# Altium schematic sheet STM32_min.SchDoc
size A; SheetNumber: 2; SheetTotal: 5
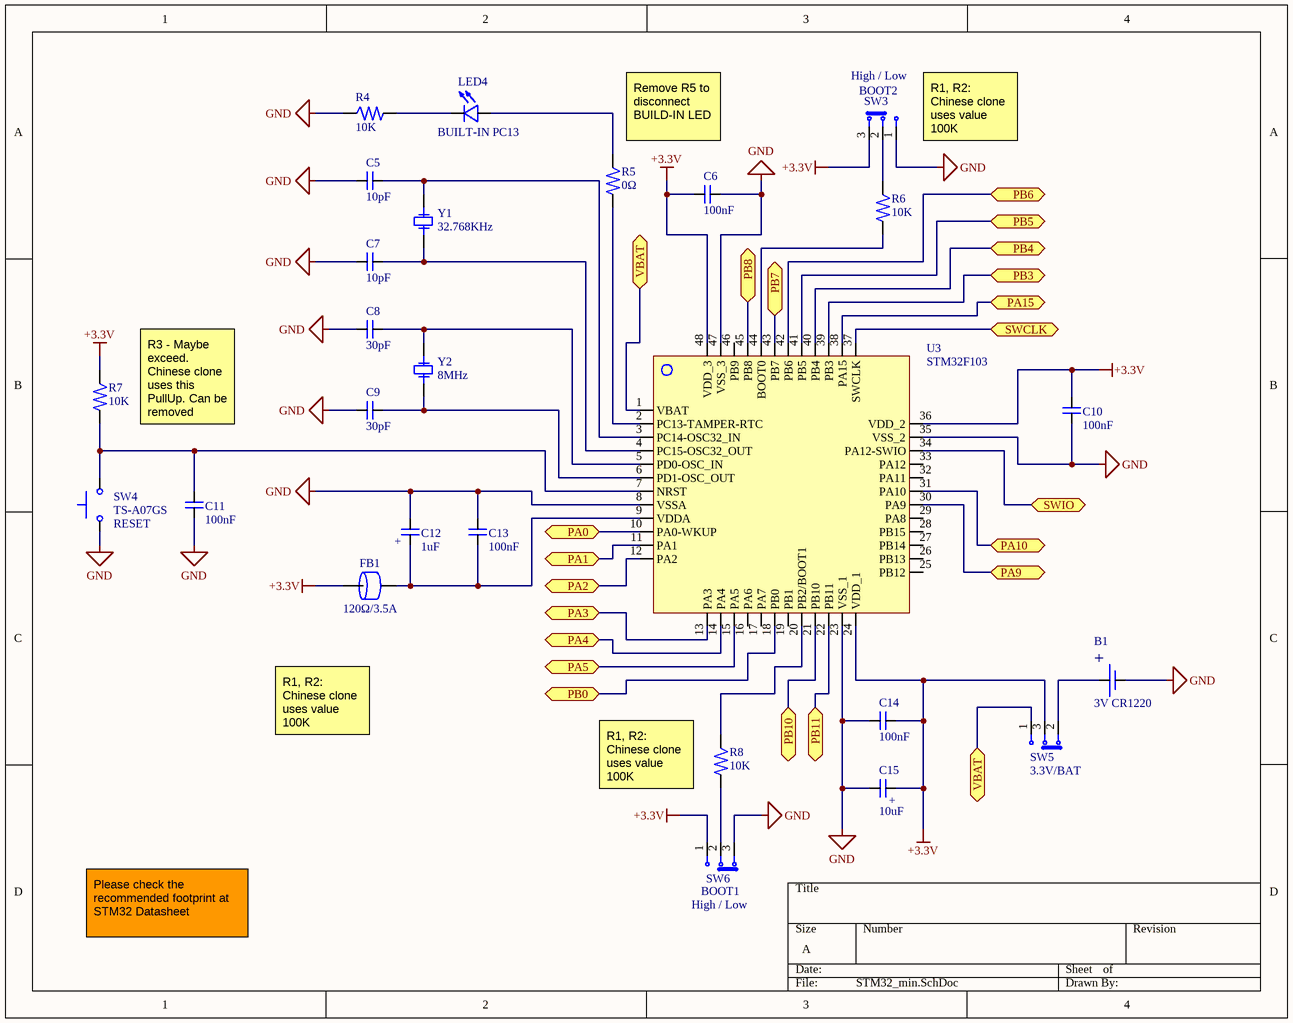
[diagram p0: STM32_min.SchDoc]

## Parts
B1  3V CR1220  [THT_BH-25T-GLD]
C5  10pF  [SMT_CAP_CER_MODEL_0805(2012)_SAMSUNG]
C6  100nF  [SMT_CAP_MODEL_1206(3216)_SAMSUNG]
C7  10pF  [SMT_CAP_CER_MODEL_0805(2012)_SAMSUNG]
C8  30pF  [SMT_CAP_MODEL_1206(3216)_SAMSUNG]
C9  30pF  [SMT_CAP_MODEL_1206(3216)_SAMSUNG]
C10  100nF  [SMT_CAP_MODEL_1206(3216)_SAMSUNG]
C11  100nF  [SMT_CAP_MODEL_1206(3216)_SAMSUNG]
C12  1uF  [SMT_CAP_TANT_MODEL_1206(3216)_KYOCERA]
C13  100nF  [SMT_CAP_MODEL_1206(3216)_SAMSUNG]
C14  100nF  [SMT_CAP_MODEL_1206(3216)_SAMSUNG]
C15  10uF  [SMT_CAP_TANT_MODEL_1210(3528)_KYOCERA]
FB1  120Ω/3.5A  [SMT_FERR_BEAD_MODEL_1206(3216)_MURATA]
LED4  BUILT-IN PC13  [DIOM2012X18N]
R4  10K  [SMT_RES_MODEL_1206(3216)_ROHM]
R5  0Ω  [SMT_RES_MODEL_1206(3216)_ROHM]
R6  10K  [SMT_RES_MODEL_1206(3216)_ROHM]
R7  10K  [SMT_RES_MODEL_1206(3216)_ROHM]
R8  10K  [SMT_RES_MODEL_1206(3216)_ROHM]
SW3  BOOT2  [SMT_SWW_SS-B90AP_DAWNING]
SW4  TS-A07GS  [SMT_TSW-A07GS]
SW5  3.3V/BAT  [THT_SSW_ESP1010]
SW6  BOOT1  [SMT_SWW_SS-B90AP_DAWNING]
U3  STM32F103  [SMT_IC_STM32F103]
Y1  32.768KHz  [SMT_XTAL_FC-135_EPSON]
Y2  8MHz  [SMT_XTAL_ATS08ASM-1E]

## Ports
PA0 (bidir), PA1 (bidir), PA2 (bidir), PA3 (bidir), PA4 (bidir), PA5 (bidir), PA9 (bidir), PA10 (bidir), PA15 (bidir), PB0 (bidir), PB3 (bidir), PB4 (bidir), PB5 (bidir), PB6 (bidir), PB7 (bidir), PB8 (bidir), PB10 (bidir), PB11 (bidir), SWCLK (bidir), SWIO (bidir), VBAT (bidir)

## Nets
+3.3V: C6.1 C10.1 C14.1 C15.1 FB1.1 R7.2 SW3.3 SW5.3 SW6.1 U3.24(VDD_1) U3.36(VDD_2) U3.48(VDD_3)
GND: B1.2(V-) C5.1 C6.2 C7.1 C8.1 C9.1 C10.2 C11.1 C12.2 C13.2 C14.2 C15.2 R4.2 SW3.1 SW4.1 SW6.3 U3.8(VSSA) U3.23(VSS_1) U3.35(VSS_2) U3.47(VSS_3)
PA0: U3.10(PA0-WKUP) ; port PA0
PA1: U3.11(PA1) ; port PA1
PA2: U3.12(PA2) ; port PA2
PA3: U3.13(PA3) ; port PA3
PA4: U3.14(PA4) ; port PA4
PA5: U3.15(PA5) ; port PA5
PA9: U3.30(PA9) ; port PA9
PA10: U3.31(PA10) ; port PA10
PA15: U3.38(PA15) ; port PA15
PB0: U3.18(PB0) ; port PB0
PB3: U3.39(PB3) ; port PB3
PB4: U3.40(PB4) ; port PB4
PB5: U3.41(PB5) ; port PB5
PB6: U3.42(PB6) ; port PB6
PB7: U3.43(PB7) ; port PB7
PB8: U3.45(PB8) ; port PB8
PB10: U3.21(PB10) ; port PB10
PB11: U3.22(PB11) ; port PB11
SWCLK: U3.37(SWCLK) ; port SWCLK
SWIO: U3.34(PA12-SWIO) ; port SWIO
VBAT: SW5.1 U3.1(VBAT) ; port VBAT
NetB1_1: B1.1(V+) SW5.2
NetC5_2: C5.2 U3.3(PC14-OSC32_IN) Y1.2
NetC7_2: C7.2 U3.4(PC15-OSC32_OUT) Y1.1
NetC8_2: C8.2 U3.5(PD0-OSC_IN) Y2.2
NetC9_2: C9.2 U3.6(PD1-OSC_OUT) Y2.1
NetC11_2: C11.2 R7.1 SW4.2 U3.7(NRST)
NetC12_1: C12.1 C13.1 FB1.2 U3.9(VDDA)
NetLED4_1: LED4.1 R5.2
NetLED4_2: LED4.2 R4.1
NetR5_1: R5.1 U3.2(PC13-TAMPER-RTC)
NetR6_1: R6.1 U3.44(BOOT0)
NetR6_2: R6.2 SW3.2
NetR8_1: R8.1 SW6.2
NetR8_2: R8.2 U3.20(PB2/BOOT1)

Not connected (* = marked no-connect by the designer): U3 16(PA6) 17(PA7) 19(PB1) 25(PB12) 26(PB13) 27(PB14) 28(PB15) 29(PA8) 32(PA11) 33(PA12) 46(PB9)

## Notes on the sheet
- (near SW3) High / Low
- (near R5) Remove R5 to disconnect BUILD-IN LED
- (near SW3) R1, R2: Chinese clone uses value 100K
- (near R7) R3 - Maybe exceed. Chinese clone uses this PullUp. Can be removed
- (near SW4) RESET
- R1, R2: Chinese clone uses value 100K
- (near R8) R1, R2: Chinese clone uses value 100K
- (near SW6) High / Low
- Please check the recommended footprint at STM32 Datasheet

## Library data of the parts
B1 = THT_BH-25T-GLD: Battery Holder for CR-2032 Type Battery BH-25T-GLD
C5 C7 = SMT_CAP_CER_MODEL_0805(2012)_SAMSUNG: SMT SAMSUNG Ceramic Capacitor MODEL *V *pF 0805(2012) CL21C100DBANNNC(etc.)
C6 C8-C11 C13 C14 = SMT_CAP_MODEL_1206(3216)_SAMSUNG: SMT Samsung Ceramic Capacitor MODEL *V *nF 1206(3216)  CL31B104KBCNNNC(etc.)
C12 = SMT_CAP_TANT_MODEL_1206(3216)_KYOCERA: SMT KYOCERA Tantalum Capacitor MODEL *V *uF 1206(3216) EAN_3216-18 TAJA105M016RNJ(etc.)
C15 = SMT_CAP_TANT_MODEL_1210(3528)_KYOCERA: SMT KYOCERA Tantalum Capacitor MODEL *V *uF 1210(3528)  TAJB106K016RNJ(etc.)
FB1 = SMT_FERR_BEAD_MODEL_1206(3216)_MURATA: SMT MURATA Ferrite Bead MODEL 1206(3216) BLM31PG121SN1L *Ω/*mA
LED4 = SMT_LED_0805(2012): Led Diode 0805(2012) Cathode Mark, 20mA
R4-R8 = SMT_RES_MODEL_1206(3216)_ROHM: SMT ROHM Resistor MODEL 1206(3216) 1/4W MCR18ERTJ000
SW3 SW6 = SMT_SWW_SS-B90AP_DAWNING: Slide Switch SMD 12V 50mA 2-POS SS-B90AP-W-SP2-S085
SW4 = SMT_TSW-A07GS: Tactile Switch TS-A07GS 50mA 12V
SW5 = THT_SSW_ESP1010: Slide Switch ESP1010 12V 0.5A
U3 = SMT_IC_STM32F103: MCU STM32F103x8 LQFP48 pinout
Y1 = SMT_XTAL_FC-135_EPSON: SMD Quartz Crystal EPSON FC-135 12.5pF 32.768KHz ±20.0ppm
Y2 = SMT_XTAL_ATS08ASM-1E: SMD Quartz Crystal ATS08ASM-1E 20pF 8MHz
